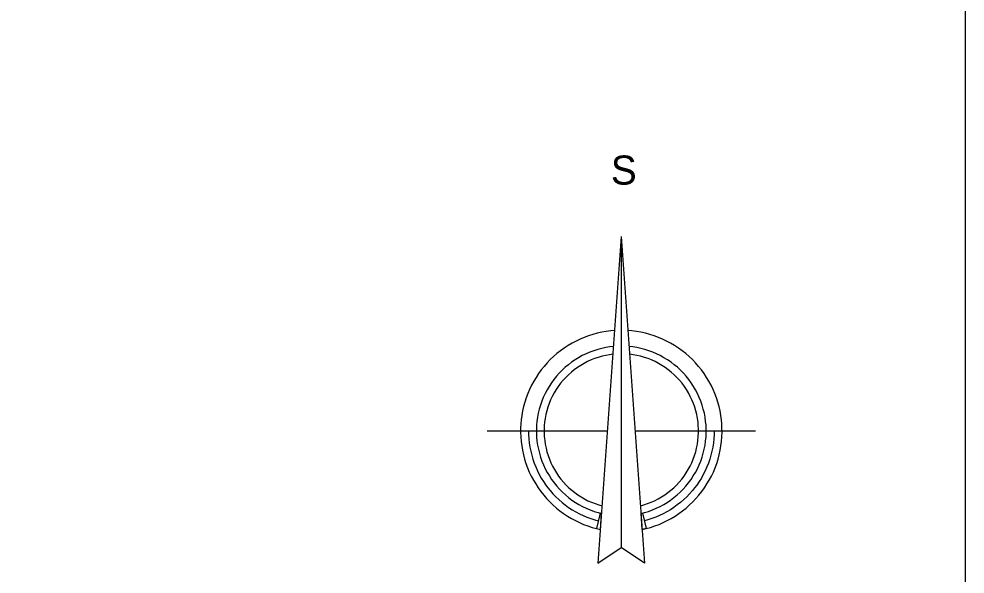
# Model space of a CAD drawing. Extents: x -574342 to -508101, y -1143544 to -1123894.
# Drawn here: x -508211 to -508109.1, y -1143385.9 to -1143326.1 of the extents above; entities that cross this region are included whole.
import ezdxf

# ---------------------------------------------------------------- set-up
doc = ezdxf.new("R2010")
doc.units = 0
doc.layers.add('Level 1', color=7, linetype='Continuous')
doc.layers.add('Level 255', color=7, linetype='Continuous')

msp = doc.modelspace()

# ---------------------------------------------------------------- linework, layer by layer
at = {"layer": 'Level 1'}
msp.add_lwpolyline([(-508703.1, -1143116.06), (-508109.1, -1143116.06), (-508109.1, -1143536.06), (-508703.1, -1143536.06)], close=True, dxfattribs=at)
at = {"layer": 'Level 255'}
for p, q in [((-508146.11, -1143349.52), (-508148.63, -1143384.7)), ((-508146.11, -1143349.52), (-508146.11, -1143383.03)), ((-508146.11, -1143349.52), (-508143.6, -1143384.7)), ((-508160.57, -1143370.46), (-508147.61, -1143370.46)), ((-508144.61, -1143370.46), (-508131.65, -1143370.46)), ((-508148.63, -1143384.7), (-508146.11, -1143383.03)), ((-508143.6, -1143384.7), (-508146.11, -1143383.03))]:
    msp.add_line(p, q, dxfattribs=at)
for points in [[(-508146.83, -1143359.64), (-508147.25, -1143359.68), (-508147.74, -1143359.74), (-508148.22, -1143359.82), (-508148.7, -1143359.93), (-508149.17, -1143360.06), (-508149.64, -1143360.21), (-508150.1, -1143360.38), (-508150.55, -1143360.57), (-508150.99, -1143360.78), (-508151.42, -1143361.01), (-508151.85, -1143361.26), (-508152.26, -1143361.52), (-508152.65, -1143361.81), (-508153.04, -1143362.12), (-508153.41, -1143362.44), (-508153.76, -1143362.77), (-508154.1, -1143363.13), (-508154.43, -1143363.5), (-508154.73, -1143363.88), (-508155.02, -1143364.28), (-508155.29, -1143364.68), (-508155.54, -1143365.1), (-508155.77, -1143365.54), (-508155.99, -1143365.98), (-508156.18, -1143366.43), (-508156.35, -1143366.89), (-508156.5, -1143367.35), (-508156.63, -1143367.83), (-508156.74, -1143368.3), (-508156.83, -1143368.79), (-508156.89, -1143369.27), (-508156.93, -1143369.69), (-508156.95, -1143370.11), (-508156.96, -1143370.6), (-508156.94, -1143371.09), (-508156.9, -1143371.58), (-508156.84, -1143372.06), (-508156.76, -1143372.54), (-508156.65, -1143373.02), (-508156.52, -1143373.5), (-508156.38, -1143373.96), (-508156.21, -1143374.42), (-508156.02, -1143374.88), (-508155.81, -1143375.32), (-508155.58, -1143375.75), (-508155.33, -1143376.17), (-508155.06, -1143376.59), (-508154.78, -1143376.98), (-508154.47, -1143377.37), (-508154.15, -1143377.74), (-508153.82, -1143378.09), (-508153.47, -1143378.43), (-508153.1, -1143378.76), (-508152.72, -1143379.07), (-508152.32, -1143379.36), (-508151.91, -1143379.63), (-508151.49, -1143379.88), (-508151.06, -1143380.11), (-508150.62, -1143380.33), (-508150.17, -1143380.52), (-508149.71, -1143380.69), (-508149.25, -1143380.85), (-508148.77, -1143380.98), (-508148.37, -1143381.07)], [(-508143.86, -1143381.07), (-508143.45, -1143380.98), (-508142.97, -1143380.85), (-508142.51, -1143380.69), (-508142.05, -1143380.52), (-508141.6, -1143380.33), (-508141.16, -1143380.11), (-508140.73, -1143379.88), (-508140.31, -1143379.63), (-508139.9, -1143379.36), (-508139.51, -1143379.07), (-508139.12, -1143378.76), (-508138.76, -1143378.43), (-508138.4, -1143378.09), (-508138.07, -1143377.74), (-508137.75, -1143377.37), (-508137.44, -1143376.98), (-508137.16, -1143376.59), (-508136.89, -1143376.17), (-508136.64, -1143375.75), (-508136.41, -1143375.32), (-508136.2, -1143374.88), (-508136.01, -1143374.42), (-508135.84, -1143373.96), (-508135.7, -1143373.5), (-508135.57, -1143373.02), (-508135.47, -1143372.54), (-508135.38, -1143372.06), (-508135.32, -1143371.58), (-508135.28, -1143371.09), (-508135.26, -1143370.6), (-508135.27, -1143370.11), (-508135.29, -1143369.69), (-508135.33, -1143369.27), (-508135.39, -1143368.79), (-508135.48, -1143368.3), (-508135.59, -1143367.83), (-508135.72, -1143367.35), (-508135.87, -1143366.89), (-508136.04, -1143366.43), (-508136.23, -1143365.98), (-508136.45, -1143365.54), (-508136.68, -1143365.1), (-508136.93, -1143364.68), (-508137.2, -1143364.28), (-508137.49, -1143363.88), (-508137.8, -1143363.5), (-508138.12, -1143363.13), (-508138.46, -1143362.77), (-508138.81, -1143362.44), (-508139.18, -1143362.12), (-508139.57, -1143361.81), (-508139.96, -1143361.52), (-508140.37, -1143361.26), (-508140.8, -1143361.01), (-508141.23, -1143360.78), (-508141.67, -1143360.57), (-508142.12, -1143360.38), (-508142.58, -1143360.21), (-508143.05, -1143360.06), (-508143.52, -1143359.93), (-508144, -1143359.82), (-508144.48, -1143359.74), (-508144.97, -1143359.68), (-508145.39, -1143359.64)], [(-508146.96, -1143361.36), (-508147.34, -1143361.4), (-508147.78, -1143361.47), (-508148.22, -1143361.57), (-508148.65, -1143361.68), (-508149.08, -1143361.82), (-508149.5, -1143361.97), (-508149.91, -1143362.15), (-508150.31, -1143362.34), (-508150.71, -1143362.56), (-508151.09, -1143362.79), (-508151.46, -1143363.05), (-508151.81, -1143363.32), (-508152.16, -1143363.6), (-508152.49, -1143363.91), (-508152.8, -1143364.23), (-508153.1, -1143364.56), (-508153.38, -1143364.91), (-508153.64, -1143365.28), (-508153.88, -1143365.65), (-508154.11, -1143366.04), (-508154.32, -1143366.43), (-508154.51, -1143366.84), (-508154.67, -1143367.26), (-508154.82, -1143367.68), (-508154.94, -1143368.11), (-508155.05, -1143368.54), (-508155.13, -1143368.98), (-508155.19, -1143369.43), (-508155.23, -1143369.81), (-508155.25, -1143370.19), (-508155.25, -1143370.64), (-508155.23, -1143371.09), (-508155.19, -1143371.54), (-508155.13, -1143371.98), (-508155.04, -1143372.42), (-508154.93, -1143372.85), (-508154.81, -1143373.28), (-508154.66, -1143373.7), (-508154.49, -1143374.12), (-508154.3, -1143374.53), (-508154.09, -1143374.92), (-508153.86, -1143375.31), (-508153.62, -1143375.68), (-508153.35, -1143376.04), (-508153.07, -1143376.39), (-508152.77, -1143376.72), (-508152.46, -1143377.04), (-508152.13, -1143377.35), (-508151.78, -1143377.63), (-508151.43, -1143377.9), (-508151.05, -1143378.15), (-508150.67, -1143378.39), (-508150.28, -1143378.6), (-508149.88, -1143378.79), (-508149.46, -1143378.97), (-508149.04, -1143379.12), (-508148.61, -1143379.26), (-508148.24, -1143379.35)], [(-508143.98, -1143379.35), (-508143.61, -1143379.26), (-508143.18, -1143379.12), (-508142.76, -1143378.97), (-508142.35, -1143378.79), (-508141.94, -1143378.6), (-508141.55, -1143378.39), (-508141.17, -1143378.15), (-508140.8, -1143377.9), (-508140.44, -1143377.63), (-508140.09, -1143377.35), (-508139.76, -1143377.04), (-508139.45, -1143376.72), (-508139.15, -1143376.39), (-508138.87, -1143376.04), (-508138.6, -1143375.68), (-508138.36, -1143375.31), (-508138.13, -1143374.92), (-508137.92, -1143374.53), (-508137.73, -1143374.12), (-508137.56, -1143373.7), (-508137.41, -1143373.28), (-508137.29, -1143372.85), (-508137.18, -1143372.42), (-508137.09, -1143371.98), (-508137.03, -1143371.54), (-508136.99, -1143371.09), (-508136.97, -1143370.64), (-508136.97, -1143370.19), (-508136.99, -1143369.81), (-508137.03, -1143369.43), (-508137.09, -1143368.98), (-508137.17, -1143368.54), (-508137.28, -1143368.11), (-508137.4, -1143367.68), (-508137.55, -1143367.26), (-508137.72, -1143366.84), (-508137.9, -1143366.43), (-508138.11, -1143366.04), (-508138.34, -1143365.65), (-508138.58, -1143365.28), (-508138.84, -1143364.91), (-508139.13, -1143364.56), (-508139.42, -1143364.23), (-508139.74, -1143363.91), (-508140.06, -1143363.6), (-508140.41, -1143363.32), (-508140.76, -1143363.05), (-508141.13, -1143362.79), (-508141.52, -1143362.56), (-508141.91, -1143362.34), (-508142.31, -1143362.15), (-508142.72, -1143361.97), (-508143.14, -1143361.82), (-508143.57, -1143361.68), (-508144, -1143361.57), (-508144.44, -1143361.47), (-508144.88, -1143361.4), (-508145.26, -1143361.36)], [(-508147.02, -1143362.2), (-508147.37, -1143362.24), (-508147.78, -1143362.32), (-508148.19, -1143362.41), (-508148.59, -1143362.53), (-508148.99, -1143362.66), (-508149.37, -1143362.81), (-508149.75, -1143362.99), (-508150.12, -1143363.18), (-508150.48, -1143363.39), (-508150.83, -1143363.62), (-508151.17, -1143363.86), (-508151.49, -1143364.12), (-508151.8, -1143364.4), (-508152.1, -1143364.69), (-508152.38, -1143365), (-508152.65, -1143365.32), (-508152.9, -1143365.66), (-508153.13, -1143366), (-508153.34, -1143366.36), (-508153.54, -1143366.73), (-508153.72, -1143367.11), (-508153.88, -1143367.49), (-508154.02, -1143367.88), (-508154.14, -1143368.28), (-508154.24, -1143368.69), (-508154.31, -1143369.1), (-508154.37, -1143369.51), (-508154.4, -1143369.87), (-508154.42, -1143370.23), (-508154.42, -1143370.65), (-508154.4, -1143371.06), (-508154.36, -1143371.48), (-508154.3, -1143371.89), (-508154.22, -1143372.3), (-508154.12, -1143372.7), (-508154, -1143373.1), (-508153.85, -1143373.49), (-508153.69, -1143373.88), (-508153.51, -1143374.25), (-508153.31, -1143374.62), (-508153.1, -1143374.98), (-508152.86, -1143375.32), (-508152.61, -1143375.65), (-508152.34, -1143375.97), (-508152.06, -1143376.28), (-508151.76, -1143376.57), (-508151.44, -1143376.84), (-508151.12, -1143377.1), (-508150.78, -1143377.34), (-508150.43, -1143377.57), (-508150.07, -1143377.78), (-508149.7, -1143377.97), (-508149.32, -1143378.14), (-508148.93, -1143378.29), (-508148.53, -1143378.42), (-508148.18, -1143378.51)], [(-508144.04, -1143378.51), (-508143.69, -1143378.42), (-508143.29, -1143378.29), (-508142.91, -1143378.14), (-508142.53, -1143377.97), (-508142.15, -1143377.78), (-508141.79, -1143377.57), (-508141.44, -1143377.34), (-508141.1, -1143377.1), (-508140.78, -1143376.84), (-508140.46, -1143376.57), (-508140.16, -1143376.28), (-508139.88, -1143375.97), (-508139.61, -1143375.65), (-508139.36, -1143375.32), (-508139.13, -1143374.98), (-508138.91, -1143374.62), (-508138.71, -1143374.25), (-508138.53, -1143373.88), (-508138.37, -1143373.49), (-508138.22, -1143373.1), (-508138.1, -1143372.7), (-508138, -1143372.3), (-508137.92, -1143371.89), (-508137.86, -1143371.48), (-508137.82, -1143371.06), (-508137.8, -1143370.65), (-508137.8, -1143370.23), (-508137.82, -1143369.87), (-508137.85, -1143369.51), (-508137.91, -1143369.1), (-508137.99, -1143368.69), (-508138.09, -1143368.28), (-508138.2, -1143367.88), (-508138.34, -1143367.49), (-508138.5, -1143367.11), (-508138.68, -1143366.73), (-508138.88, -1143366.36), (-508139.09, -1143366), (-508139.32, -1143365.66), (-508139.57, -1143365.32), (-508139.84, -1143365), (-508140.12, -1143364.69), (-508140.42, -1143364.4), (-508140.73, -1143364.12), (-508141.05, -1143363.86), (-508141.39, -1143363.62), (-508141.74, -1143363.39), (-508142.1, -1143363.18), (-508142.47, -1143362.99), (-508142.85, -1143362.81), (-508143.23, -1143362.66), (-508143.63, -1143362.53), (-508144.03, -1143362.41), (-508144.44, -1143362.32), (-508144.85, -1143362.24), (-508145.2, -1143362.2)], [(-508156.1, -1143370.46), (-508156.1, -1143370.85), (-508156.07, -1143371.3), (-508156.02, -1143371.74), (-508155.96, -1143372.19), (-508155.87, -1143372.62), (-508155.76, -1143373.06), (-508155.64, -1143373.49), (-508155.49, -1143373.91), (-508155.33, -1143374.33), (-508155.15, -1143374.74), (-508154.95, -1143375.14), (-508154.73, -1143375.53), (-508154.49, -1143375.91), (-508154.24, -1143376.28), (-508154.01, -1143376.59), (-508153.76, -1143376.89), (-508153.47, -1143377.23), (-508153.16, -1143377.55), (-508152.83, -1143377.86), (-508152.49, -1143378.15), (-508152.14, -1143378.43), (-508151.78, -1143378.69), (-508151.41, -1143378.94), (-508151.02, -1143379.17), (-508150.63, -1143379.38), (-508150.23, -1143379.57), (-508149.81, -1143379.75), (-508149.39, -1143379.9), (-508148.97, -1143380.04), (-508148.59, -1143380.14)], [(-508136.12, -1143370.46), (-508136.12, -1143370.85), (-508136.15, -1143371.3), (-508136.2, -1143371.74), (-508136.27, -1143372.19), (-508136.35, -1143372.62), (-508136.46, -1143373.06), (-508136.59, -1143373.49), (-508136.73, -1143373.91), (-508136.89, -1143374.33), (-508137.08, -1143374.74), (-508137.28, -1143375.14), (-508137.49, -1143375.53), (-508137.73, -1143375.91), (-508137.98, -1143376.28), (-508138.22, -1143376.59), (-508138.46, -1143376.89), (-508138.76, -1143377.23), (-508139.07, -1143377.55), (-508139.39, -1143377.86), (-508139.73, -1143378.15), (-508140.08, -1143378.43), (-508140.44, -1143378.69), (-508140.81, -1143378.94), (-508141.2, -1143379.17), (-508141.59, -1143379.38), (-508142, -1143379.57), (-508142.41, -1143379.75), (-508142.83, -1143379.9), (-508143.25, -1143380.04), (-508143.63, -1143380.14)]]:
    msp.add_lwpolyline(points, dxfattribs=at)
for points in [[(-508148.24, -1143379.35), (-508148.38, -1143379.32), (-508148.8, -1143380.97), (-508148.37, -1143381.07)], [(-508143.98, -1143379.35), (-508143.84, -1143379.32), (-508143.42, -1143380.97), (-508143.86, -1143381.07)]]:
    msp.add_lwpolyline(points, close=True, dxfattribs=at)

# ---------------------------------------------------------------- texts
msp.add_text('S', height=3.13, dxfattribs=at).set_placement((-508147.24, -1143343.91))

doc.saveas('drawing.dxf')
